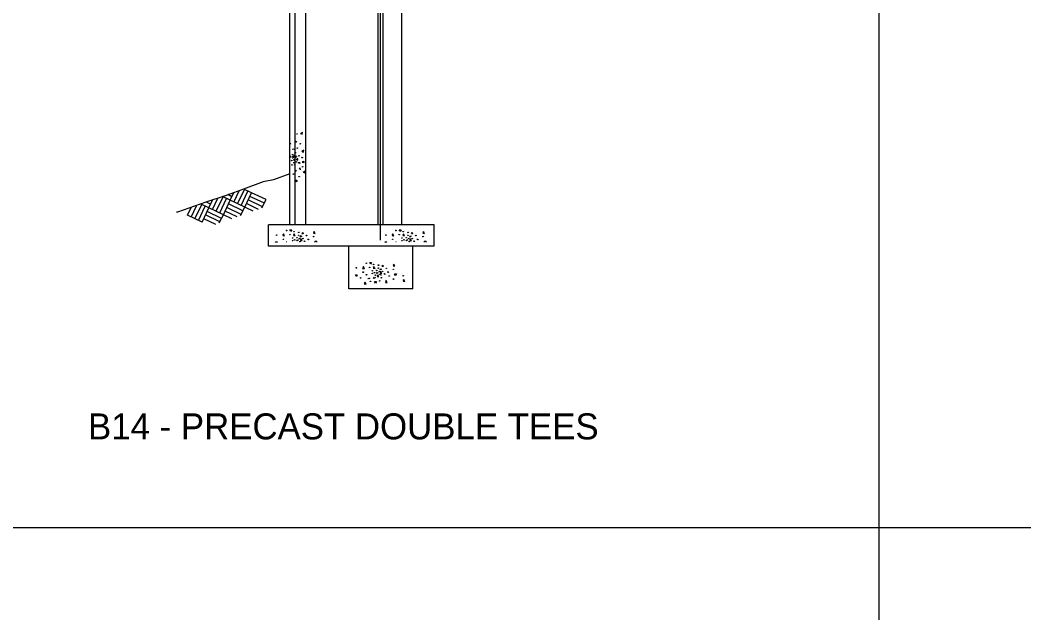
# Model space of a CAD drawing. Extents: x -0.04 to 2.79, y -0.02 to 1.81.
# Drawn here: x 0.9741 to 1.3759, y 0.4542 to 0.6917 of the extents above; entities that cross this region are included whole.
import ezdxf

# ---------------------------------------------------------------- set-up
doc = ezdxf.new("R2010")
doc.units = 0
doc.layers.add('Level 1', color=7, linetype='Continuous')
doc.layers.add('Level 2', color=7, linetype='Continuous')

msp = doc.modelspace()

# ---------------------------------------------------------------- linework, layer by layer
for p, q in [((1.3178411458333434, 1.7318499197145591), (1.3178411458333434, 0.08028109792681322)), ((0.11656352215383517, 0.48847341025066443), (2.517841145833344, 0.48847341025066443))]:
    msp.add_line(p, q)
at = {"layer": 'Level 1'}
for p, q in [((1.082047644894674, 0.609645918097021), (1.082047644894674, 0.8019168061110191)), ((1.0842348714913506, 0.609645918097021), (1.0842348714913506, 0.8019168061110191)), ((1.0884726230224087, 0.609645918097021), (1.0884726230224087, 0.8019168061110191)), ((1.1184102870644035, 0.6034943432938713), (1.1184102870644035, 0.798635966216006)), ((1.117385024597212, 0.609645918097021), (1.117385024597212, 0.7954918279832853)), ((1.119435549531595, 0.609645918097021), (1.119435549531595, 0.7954918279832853)), ((1.1269541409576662, 0.609645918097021), (1.1269541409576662, 0.7954918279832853)), ((1.0596285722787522, 0.6188049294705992), (1.061815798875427, 0.6233160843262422)), ((1.0610639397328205, 0.6181214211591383), (1.0638663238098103, 0.6238628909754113)), ((1.0625676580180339, 0.6174379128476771), (1.0653016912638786, 0.6231793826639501)), ((1.0667370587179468, 0.6224958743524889), (1.063661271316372, 0.6239995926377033)), ((1.0503328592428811, 0.6179163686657), (1.0486924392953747, 0.6187365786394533)), ((1.0496493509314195, 0.6164810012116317), (1.0511530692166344, 0.6195567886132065)), ((1.0496493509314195, 0.6164810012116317), (1.0511530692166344, 0.6195567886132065)), ((1.0510163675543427, 0.6193517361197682), (1.0508113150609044, 0.6194884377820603)), ((1.051084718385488, 0.6157974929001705), (1.0532719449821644, 0.6203086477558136)), ((1.052520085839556, 0.6151139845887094), (1.0553224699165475, 0.6208554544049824)), ((1.054023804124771, 0.6144304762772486), (1.0567578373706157, 0.6201719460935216)), ((1.058193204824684, 0.6194884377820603), (1.055117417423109, 0.6209921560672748)), ((1.0554591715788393, 0.6136786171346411), (1.058193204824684, 0.6194884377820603)), ((1.058876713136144, 0.6209238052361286), (1.0572362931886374, 0.6217440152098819)), ((1.058193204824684, 0.6194884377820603), (1.0596969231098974, 0.6225642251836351)), ((1.058193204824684, 0.6194884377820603), (1.0596969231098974, 0.6225642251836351)), ((1.0673522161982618, 0.6151139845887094), (1.058193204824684, 0.6194884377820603)), ((1.0595602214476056, 0.6223591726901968), (1.0593551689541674, 0.6224958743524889)), ((1.064003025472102, 0.6167544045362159), (1.0667370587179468, 0.6224958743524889)), ((1.0711798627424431, 0.6168911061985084), (1.0653700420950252, 0.6196251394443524)), ((1.0718633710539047, 0.6183264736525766), (1.0660535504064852, 0.6210605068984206)), ((1.0725468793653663, 0.6197618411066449), (1.0667370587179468, 0.6224958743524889)), ((1.07090645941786, 0.6164126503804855), (1.0725468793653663, 0.6197618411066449)), ((1.0411054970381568, 0.6134735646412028), (1.0426092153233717, 0.6165493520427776)), ((1.042540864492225, 0.6127900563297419), (1.0447280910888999, 0.6173012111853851)), ((1.0439762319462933, 0.6121065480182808), (1.046778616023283, 0.6178480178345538)), ((1.0454799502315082, 0.6113546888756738), (1.0482139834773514, 0.6171645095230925)), ((1.0496493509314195, 0.6164810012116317), (1.0465735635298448, 0.6179847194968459)), ((1.0469153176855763, 0.6106711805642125), (1.0496493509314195, 0.6164810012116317)), ((1.0547756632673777, 0.6122432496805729), (1.0489658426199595, 0.6150456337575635)), ((1.0554591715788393, 0.6136786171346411), (1.0496493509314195, 0.6164810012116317)), ((1.0609272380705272, 0.6128584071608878), (1.0561426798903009, 0.6151823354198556)), ((1.0626360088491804, 0.6138153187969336), (1.0568261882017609, 0.6166177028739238)), ((1.063319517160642, 0.6153190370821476), (1.0575096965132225, 0.6180530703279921)), ((1.0623626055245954, 0.613405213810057), (1.064003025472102, 0.6167544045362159)), ((1.0694710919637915, 0.6158658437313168), (1.0646865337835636, 0.6181897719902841)), ((1.0469153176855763, 0.6106711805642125), (1.0411054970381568, 0.6134735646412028)), ((1.0523833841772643, 0.6098509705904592), (1.0475988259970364, 0.6121065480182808)), ((1.0540921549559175, 0.6108078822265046), (1.048282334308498, 0.6136102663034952)), ((1.0538187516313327, 0.610397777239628), (1.0554591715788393, 0.6136786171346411)), ((1.0588083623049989, 0.6121065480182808), (1.0554591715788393, 0.6136786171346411)), ((1.1398040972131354, 0.609645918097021), (1.0735037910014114, 0.609645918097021)), ((1.0735037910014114, 0.6011020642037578), (1.0735037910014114, 0.609645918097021)), ((1.1398040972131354, 0.6011020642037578), (1.1398040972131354, 0.609645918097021)), ((1.105628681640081, 0.6011020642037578), (1.0735037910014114, 0.6011020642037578)), ((1.105628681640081, 0.5840143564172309), (1.105628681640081, 0.6011020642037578)), ((1.131260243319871, 0.6011020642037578), (1.105628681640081, 0.6011020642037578)), ((1.131260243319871, 0.5840143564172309), (1.131260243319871, 0.6011020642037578)), ((1.1398040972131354, 0.6011020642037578), (1.131260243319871, 0.6011020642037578)), ((1.131260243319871, 0.5840143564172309), (1.105628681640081, 0.5840143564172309))]:
    msp.add_line(p, q, dxfattribs=at)
msp.add_lwpolyline([(1.082047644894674, 0.6300828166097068), (1.075485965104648, 0.6276221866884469), (1.0714532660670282, 0.6268703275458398), (1.0624993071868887, 0.6235894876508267), (1.0565527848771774, 0.6214706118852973), (1.0484873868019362, 0.6187365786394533), (1.037141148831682, 0.6147038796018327), (1.0367310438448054, 0.6147038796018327)], dxfattribs=at)
at = {"layer": 'Level 2'}
for points in [[(1.0847133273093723, 0.642932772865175), (1.084166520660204, 0.6425910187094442), (1.084166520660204, 0.6433428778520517), (1.0848500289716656, 0.642932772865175)], [(1.086353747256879, 0.646281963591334), (1.0870372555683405, 0.6459402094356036), (1.087105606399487, 0.6466237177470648), (1.086353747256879, 0.6460769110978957)], [(1.0834146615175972, 0.639651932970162), (1.0832779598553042, 0.6399936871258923), (1.0836197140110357, 0.6401303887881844), (1.0834830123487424, 0.639651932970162)], [(1.0869005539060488, 0.639173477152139), (1.0875840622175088, 0.6388317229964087), (1.0876524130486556, 0.6395152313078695), (1.0869005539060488, 0.6390367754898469)], [(1.0823893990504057, 0.6372596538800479), (1.0825261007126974, 0.6367128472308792)], [(1.0825261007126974, 0.6367128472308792), (1.0823893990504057, 0.6367811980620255)], [(1.0831412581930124, 0.6371229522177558), (1.083824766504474, 0.6367811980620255), (1.083893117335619, 0.6374647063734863), (1.0831412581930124, 0.6369178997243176)], [(1.0840981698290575, 0.6353458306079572), (1.0834830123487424, 0.6356875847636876), (1.083893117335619, 0.635892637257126), (1.0840981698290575, 0.6353458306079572)], [(1.0843032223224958, 0.6382849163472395), (1.0839614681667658, 0.6384899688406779), (1.0843032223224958, 0.6387633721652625), (1.0843032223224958, 0.6383532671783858)], [(1.0845766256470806, 0.635892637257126), (1.0852601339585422, 0.6355508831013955), (1.0853284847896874, 0.6362343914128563), (1.0845766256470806, 0.6357559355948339)], [(1.087789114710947, 0.6347990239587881), (1.0872423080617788, 0.6344572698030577), (1.0872423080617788, 0.6352091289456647), (1.0879258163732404, 0.6347990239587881)], [(1.0860803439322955, 0.6341838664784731), (1.0854651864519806, 0.6345256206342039), (1.0858752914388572, 0.6347306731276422), (1.0860803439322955, 0.6341838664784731)], [(1.0860803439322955, 0.6319282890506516), (1.0858752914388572, 0.6322700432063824), (1.0860803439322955, 0.6325434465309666), (1.0862170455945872, 0.6317232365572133)], [(1.087447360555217, 0.6307663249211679), (1.0881308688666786, 0.6304245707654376), (1.0881992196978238, 0.6311080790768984), (1.087447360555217, 0.6305612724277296)], [(1.0850550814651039, 0.6272120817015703), (1.084439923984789, 0.6268703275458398), (1.084439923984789, 0.6276221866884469), (1.0851917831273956, 0.6272120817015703)], [(1.0823893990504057, 0.6071169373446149), (1.082047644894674, 0.607663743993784), (1.0827995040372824, 0.607663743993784), (1.0823893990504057, 0.6069802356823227)], [(1.0918218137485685, 0.6069802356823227), (1.091480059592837, 0.6062967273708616), (1.092231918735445, 0.6062283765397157), (1.0916851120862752, 0.6069802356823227)], [(1.1262022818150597, 0.6071169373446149), (1.1258605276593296, 0.607663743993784), (1.1266123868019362, 0.607663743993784), (1.1262022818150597, 0.6069802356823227)], [(1.1356346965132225, 0.6069802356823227), (1.1352929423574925, 0.6062967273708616), (1.1359764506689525, 0.6062283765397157), (1.135429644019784, 0.6069802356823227)], [(1.0763745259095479, 0.6027424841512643), (1.0763745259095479, 0.6028108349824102), (1.0771263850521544, 0.6028108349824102), (1.0770580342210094, 0.6027424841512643)], [(1.0795870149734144, 0.6060233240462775), (1.0792452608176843, 0.6053398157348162), (1.079928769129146, 0.60527146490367), (1.079381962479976, 0.6060233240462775)], [(1.083824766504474, 0.6060916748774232), (1.0834830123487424, 0.6054081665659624), (1.0842348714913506, 0.6053398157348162), (1.0836880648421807, 0.6060916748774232)], [(1.0848500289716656, 0.6032209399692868), (1.0851917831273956, 0.6037677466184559), (1.0853968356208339, 0.6033576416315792), (1.0848500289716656, 0.6032209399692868)], [(1.0862170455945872, 0.6047246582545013), (1.0865587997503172, 0.6053398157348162), (1.0867638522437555, 0.6049297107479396), (1.0862170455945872, 0.6047246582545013)], [(1.0866271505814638, 0.6041095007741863), (1.0862853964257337, 0.6034259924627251), (1.086968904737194, 0.6033576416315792), (1.0864220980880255, 0.6041095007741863)], [(1.0873106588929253, 0.6066384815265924), (1.087447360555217, 0.6060916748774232), (1.0869005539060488, 0.6060916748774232)], [(1.0869005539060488, 0.6062283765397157), (1.0873106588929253, 0.6065701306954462)], [(1.087789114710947, 0.6030158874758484), (1.0879941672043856, 0.603289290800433), (1.0882675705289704, 0.6030158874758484), (1.0878574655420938, 0.6029475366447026)], [(1.0891561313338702, 0.603904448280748), (1.0894978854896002, 0.6039727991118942), (1.089634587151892, 0.6036310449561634), (1.0891561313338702, 0.6038360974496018)], [(1.0923002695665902, 0.6027424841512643), (1.092095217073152, 0.603152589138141), (1.09284707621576, 0.603152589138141), (1.0925736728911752, 0.6027424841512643)], [(1.1201874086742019, 0.6027424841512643), (1.1201190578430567, 0.6028108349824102), (1.1208709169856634, 0.6028108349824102), (1.1208025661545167, 0.6027424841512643)], [(1.1233315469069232, 0.6060233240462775), (1.1229897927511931, 0.6053398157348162), (1.1237416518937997, 0.60527146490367), (1.1231948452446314, 0.6060233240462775)], [(1.1276376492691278, 0.6060916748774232), (1.1272958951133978, 0.6054081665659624), (1.127979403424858, 0.6053398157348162), (1.1274325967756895, 0.6060916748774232)], [(1.1285945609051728, 0.6032209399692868), (1.1289363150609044, 0.6037677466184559), (1.1291413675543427, 0.6033576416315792), (1.1285945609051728, 0.6032209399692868)], [(1.1300299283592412, 0.6047246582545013), (1.1303716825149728, 0.6053398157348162), (1.1305083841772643, 0.6049297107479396), (1.1300299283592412, 0.6047246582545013)], [(1.1303716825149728, 0.6041095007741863), (1.1300299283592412, 0.6034259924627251), (1.1307134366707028, 0.6033576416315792), (1.1302349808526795, 0.6041095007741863)], [(1.1310551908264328, 0.6066384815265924), (1.1311918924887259, 0.6060916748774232), (1.1307134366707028, 0.6060916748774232)], [(1.1307134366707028, 0.6062283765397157), (1.1310551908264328, 0.6065701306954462)], [(1.1315336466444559, 0.6030158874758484), (1.131807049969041, 0.603289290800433), (1.1320804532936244, 0.6030158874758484), (1.1316019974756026, 0.6029475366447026)], [(1.1329006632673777, 0.603904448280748), (1.133242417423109, 0.6039727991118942), (1.1334474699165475, 0.6036310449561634), (1.1329006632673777, 0.6038360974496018)], [(1.136044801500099, 0.6027424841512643), (1.1358397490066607, 0.603152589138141), (1.1365916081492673, 0.603152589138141), (1.136386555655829, 0.6027424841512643)], [(1.1115068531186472, 0.592899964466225), (1.1111650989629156, 0.5922164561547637), (1.111916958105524, 0.5921481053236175), (1.111370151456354, 0.592899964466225)], [(1.1143775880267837, 0.5939935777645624), (1.114035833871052, 0.5945403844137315), (1.1147876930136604, 0.5945403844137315), (1.1143775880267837, 0.5938568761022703)], [(1.115812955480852, 0.5929683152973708), (1.1154712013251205, 0.5922848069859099), (1.116154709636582, 0.5922164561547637), (1.1156079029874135, 0.5929683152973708)], [(1.1167698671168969, 0.5900975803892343), (1.1171116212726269, 0.5906443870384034), (1.1173166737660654, 0.5902342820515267), (1.1167698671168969, 0.5900975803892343)], [(1.1182052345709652, 0.5916012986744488), (1.1185469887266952, 0.5922164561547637), (1.1186836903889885, 0.591806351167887), (1.1182052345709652, 0.5916012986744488)], [(1.1185469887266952, 0.5909861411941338), (1.1182052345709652, 0.5903026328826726), (1.1188887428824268, 0.5902342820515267), (1.1184102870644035, 0.5909861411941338)], [(1.1192304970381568, 0.5935151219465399), (1.1193671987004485, 0.5929683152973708), (1.1188887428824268, 0.5929683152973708)], [(1.1188887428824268, 0.5931050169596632), (1.1192304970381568, 0.5934467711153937)], [(1.1210759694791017, 0.5907810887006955), (1.1214177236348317, 0.5908494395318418), (1.12162277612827, 0.590507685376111), (1.1210759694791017, 0.5907127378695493)], [(1.1238100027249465, 0.5938568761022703), (1.123468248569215, 0.5931733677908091), (1.1241517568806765, 0.5931050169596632), (1.1236049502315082, 0.5938568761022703)], [(1.1086361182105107, 0.5891406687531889), (1.108294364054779, 0.5896874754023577), (1.1090462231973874, 0.5896874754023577), (1.1086361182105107, 0.5890039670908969)], [(1.1121903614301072, 0.5866800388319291), (1.1118486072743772, 0.5859965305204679), (1.112600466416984, 0.585928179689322), (1.1120536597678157, 0.5866800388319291)], [(1.113352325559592, 0.5881154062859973), (1.113694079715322, 0.5883204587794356), (1.114035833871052, 0.5881154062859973), (1.1132156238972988, 0.5879787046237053)], [(1.1156079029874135, 0.5881154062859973), (1.1159496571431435, 0.5886622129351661), (1.116154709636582, 0.5882521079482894), (1.1156079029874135, 0.5881154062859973)], [(1.1162914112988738, 0.5863382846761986), (1.1159496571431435, 0.5869534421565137), (1.1167015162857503, 0.5869534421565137), (1.1162914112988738, 0.5862699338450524)], [(1.117385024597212, 0.5896191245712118), (1.1170432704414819, 0.5889356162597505), (1.117726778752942, 0.5888672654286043), (1.1171799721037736, 0.5896191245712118)], [(1.11970895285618, 0.5898925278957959), (1.1199823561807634, 0.5901659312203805), (1.1202557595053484, 0.5898925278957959), (1.119777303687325, 0.5898241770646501)], [(1.120665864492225, 0.587295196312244), (1.120324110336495, 0.5866116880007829), (1.121007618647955, 0.586543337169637), (1.1204608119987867, 0.587295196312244)], [(1.1243568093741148, 0.5894140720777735), (1.1240150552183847, 0.5900292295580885), (1.1247669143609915, 0.5900292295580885), (1.1243568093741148, 0.589277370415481)], [(1.1277060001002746, 0.5877736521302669), (1.127364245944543, 0.5870901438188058), (1.1280477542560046, 0.5870217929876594), (1.1275692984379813, 0.5877736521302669)]]:
    msp.add_lwpolyline(points, dxfattribs=at)
for centre in [(1.084926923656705, 0.6460427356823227), (1.0850465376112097, 0.640403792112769), (1.086259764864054, 0.642129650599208), (1.0828080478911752, 0.6353970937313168), (1.0831498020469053, 0.6378064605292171), (1.0831498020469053, 0.6364223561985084), (1.0843630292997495, 0.6365932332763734), (1.08465352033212, 0.6371229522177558), (1.0847047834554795, 0.6348673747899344), (1.0857471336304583, 0.6372938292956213), (1.0870116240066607, 0.63661032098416), (1.0829276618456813, 0.6336712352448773), (1.083679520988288, 0.6345256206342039), (1.084021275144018, 0.6336712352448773), (1.0845339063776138, 0.6313131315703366), (1.0871825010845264, 0.6329193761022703), (1.0834915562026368, 0.6299973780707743), (1.0857983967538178, 0.6289550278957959), (1.0807660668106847, 0.6073817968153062), (1.0836880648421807, 0.60692042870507), (1.0856360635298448, 0.6066299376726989), (1.1245105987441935, 0.6073817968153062), (1.1274325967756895, 0.60692042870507), (1.1293805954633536, 0.6066299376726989), (1.0767846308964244, 0.6055534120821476), (1.0795015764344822, 0.6038275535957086), (1.0820818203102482, 0.6057242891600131), (1.083175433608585, 0.604391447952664), (1.083175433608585, 0.6032978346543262), (1.0840298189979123, 0.603639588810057), (1.0849012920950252, 0.6045110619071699), (1.0855848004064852, 0.6054337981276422), (1.0859265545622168, 0.6041693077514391), (1.086097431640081, 0.6029560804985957), (1.0873106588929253, 0.6041693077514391), (1.0887460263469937, 0.605365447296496), (1.0915654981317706, 0.604972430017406), (1.1205291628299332, 0.6055534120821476), (1.123246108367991, 0.6038275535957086), (1.1258263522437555, 0.6057242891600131), (1.1269199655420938, 0.604391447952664), (1.1269199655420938, 0.6032978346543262), (1.1277743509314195, 0.603639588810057), (1.1286458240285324, 0.6045110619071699), (1.129329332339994, 0.6054337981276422), (1.129671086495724, 0.6041693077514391), (1.12984196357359, 0.6029560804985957), (1.1310551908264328, 0.6041693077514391), (1.132490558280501, 0.605365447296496), (1.1353100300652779, 0.604972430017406), (1.1087044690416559, 0.5924300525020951), (1.1114214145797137, 0.5907041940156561), (1.1126859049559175, 0.5942584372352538), (1.1140016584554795, 0.5926009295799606), (1.1150952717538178, 0.5912680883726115), (1.1156079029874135, 0.5937970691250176), (1.1159496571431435, 0.5905162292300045), (1.1168211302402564, 0.5913877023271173), (1.117504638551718, 0.5923104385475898), (1.1175559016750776, 0.5935065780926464), (1.117846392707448, 0.5910459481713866), (1.1192304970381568, 0.5910459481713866), (1.120665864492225, 0.5922420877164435), (1.1234853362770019, 0.5918490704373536), (1.1103790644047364, 0.588397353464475), (1.112737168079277, 0.5896618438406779), (1.1143434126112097, 0.5870132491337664), (1.1150952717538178, 0.5901744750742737), (1.1162914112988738, 0.5894909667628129), (1.118017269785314, 0.5898327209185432), (1.1180343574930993, 0.5871841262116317), (1.1185469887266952, 0.5895422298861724), (1.118717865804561, 0.5884486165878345), (1.1218278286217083, 0.5891492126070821), (1.1235536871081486, 0.5879359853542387), (1.1274667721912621, 0.5892688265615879)]:
    msp.add_circle(centre, 0.00011107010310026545, dxfattribs=at)
for centre, start, end in [((1.0823210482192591, 0.6420442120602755), 344.7448805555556, 63.43494722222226), ((1.0808173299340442, 0.6027766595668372), 18.434950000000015, 161.56505000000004), ((1.124561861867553, 0.6027766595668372), 18.434950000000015, 161.56505000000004)]:
    msp.add_arc(centre, 0.00011107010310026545, start, end, dxfattribs=at)

# ---------------------------------------------------------------- texts
msp.add_text('B14 - PRECAST DOUBLE TEES', height=0.010416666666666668).set_placement((1.0012897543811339, 0.5237134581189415))

doc.saveas('drawing.dxf')
